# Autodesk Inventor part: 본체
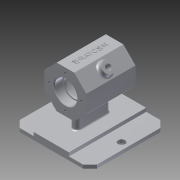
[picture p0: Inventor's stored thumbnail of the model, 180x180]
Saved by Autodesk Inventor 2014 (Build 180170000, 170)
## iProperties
Created: 2018-06
Part Number: 본체
Material: Aluminum 6061
Document SubType Name: Modeling
Designer: kh
Density: 2.71 g/cm^3
Appearance: Aluminum - Flat
Mass: 554.078 g
Surface Area: 602.069 cm^2
Volume: 204.457 cm^3
Author: kh
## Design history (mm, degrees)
sketch "Sketch1"
  geometry: 1 further point
sketch "Sketch2"
  geometry: L1 (-55, -55)-(55, -55); L2 (55, -55)-(55, 55); L3 (55, 55)-(-55, 55); L4 (-55, 55)-(-55, -55); L5 (-55, -55)-(55, 55); L6 (55, -55)-(-55, 55); 1 further point
  constraints: 12 end point, 2 midpoint, 2 parallel, 1 horizontal, 1 perpendicular
  dimensions: "d0" = 110 distance of L2.end L3.end; "d1" = 110 distance of L1.end L2.end
extrude "Extrusion1" new body sketch "Sketch2" distance "d2" = 5; taper "d3" = 0 deg
sketch "Sketch3"
  geometry: L1 (-55, 55)-(-55, -55) reference; L2 (55, -55)-(55, 55) reference; L3 (-55, -25)-(55, -25); L4 (55, -25)-(55, 25); L5 (55, 25)-(-55, 25); L6 (-55, 25)-(-55, -25); L7 (-55, -25)-(55, 25); L8 (55, -25)-(-55, 25); L9 (55, 55)-(-55, 55) reference; L10 (-55, -55)-(55, -55) reference; 1 further point
  constraints: 12 end point, 2 midpoint, 2 parallel, 1 horizontal, 1 perpendicular, 1 point on line
  dimensions: "d4" = 30 distance between parallel lines of L9 L5
extrude "Extrusion2" join sketch "Sketch3" distance "d5" = 5; taper "d6" = 0 deg
sketch "Sketch4"
  geometry: 1 further point
sketch "Sketch5" dims "d7" = 60
  geometry: L1 (12.426, 92)-(30, 74.426); L2 (30, 74.426)-(30, 49.574); L3 (30, 49.574)-(12.426, 32); L4 (12.426, 32)-(-12.426, 32); L5 (-12.426, 32)-(-30, 49.574); L6 (-30, 49.574)-(-30, 74.426); L7 (-30, 74.426)-(-12.426, 92); L8 (-12.426, 92)-(12.426, 92); 4 further points
  constraints: 16 end point, 2 vertical alignment, 1 coincident, 1 midpoint, 19 other
  dimensions: "d10" = 62 distance of point (0, 62) point (0, 0); "d12" = 17.57359 horizontal distance of L1.start L1.end
extrude "Extrusion3" join sketch "Sketch5" stored distance "d13" = 70; taper "d14" = 0 deg
sketch "Sketch6"
  geometry: 1 further point
sketch "Sketch7" dims "d15" = 46
  geometry: L1 (-74.426, 30)-(-92, 12.426) reference; L2 (-92, 12.426)-(-92, -12.426) reference; L3 (-92, -12.426)-(-74.426, -30) reference; L4 (-74.426, -30)-(-49.574, -30) reference; L5 (-49.574, -30)-(-32, -12.426) reference; L6 (-32, -12.426)-(-32, 12.426) reference; L7 (-32, 12.426)-(-49.574, 30) reference; L8 (-49.574, 30)-(-74.426, 30) reference; L9 (-49.574, 30)-(-74.426, -30); L10 (-74.426, 30)-(-49.574, -30); L11 (-92, -12.426)-(-32, 12.426); L12 (-62, 0)-(-85, 0); C1 r 16 at (-62, 0); 2 further points
  constraints: 8 end point, 2 coincident, 1 centre point, 1 horizontal alignment, 1 midpoint, 1 parallel, 1 perpendicular, 1 point on line, 2 other
  dimensions: "d34" = 32 diameter of C1
  node "Projected Loop1"
hole "Hole1" sketch "Sketch7" diameter "d16" = 3.242; stored, may be unused: countersink angle "d20" = 90 deg, drill point angle "d22" = 118 deg; dims "d17" = 8, "d18" = 4, "d19" = 2, "d21" = 10
sketch "Sketch11"
  geometry: L1 (55, 55)-(-55, 55) reference; L2 (-55, -55)-(55, -55) reference; C1 r 5 at (0, 45); 1 further point
  constraints: 1 centre point, 1 vertical alignment
  dimensions: "d25" = 10 diameter of C1; "d26" = 10 distance from line of L1 C1.centre
extrude "Extrusion4" cut sketch "Sketch11" stored distance "d27" = 70; taper "d28" = 0 deg
mirror "Mirror1"
sketch "Sketch12"
  geometry: L1 (19, 0)-(-19, 0); L2 (19, 5)-(-19, 5); L3 (-19, -5)-(19, -5); A1 r 5 centre (19, 0) between (19, -5) and (19, 5); A2 r 5 centre (-19, 0) between (-19, 5) and (-19, -5); 1 further point
  constraints: 8 end point, 4 point on circle, 4 tangent, 2 centre point, 1 horizontal, 1 midpoint, 1 parallel
  dimensions: "d29" = 38 distance of L1.end L1.start; "d30" = 5 radius of A1
extrude "Extrusion5" join sketch "Sketch12" stored distance "d31" = 70; taper "d32" = 0 deg
fillet "Fillet1" dims "d33" = 2
extrude "Extrusion6" cut sketch "Sketch7" distance "d35" = 12; taper "d36" = 0 deg
pattern_circular "Circular Pattern1" dims angle "d38" = 360 deg
hole "Hole2" diameter "d43" = 28; stored, may be unused: countersink angle "d47" = 90 deg, drill point angle "d49" = 0 deg; dims "d41" = 10, "d42" = 10, "d44" = 8, "d45" = 4, "d46" = 2, "d48" = 3
sketch "Sketch16"
  geometry: L1 (-30, -12.426)-(-30, 12.426) reference; L2 (-30, 12.426)-(-12.426, 30) reference; L3 (-12.426, 30)-(12.426, 30) reference; L4 (12.426, 30)-(30, 12.426) reference; L5 (30, 12.426)-(30, -12.426) reference; L6 (30, -12.426)-(12.426, -30) reference; L7 (12.426, -30)-(-12.426, -30) reference; L8 (-12.426, -30)-(-30, -12.426) reference; L9 (-30, -12.426)-(-30, 12.426) reference; L10 (-30, 12.426)-(30, -12.426); L11 (30, 12.426)-(-30, -12.426); C1 r 25 at (0, 0); 2 further points
  constraints: 4 end point, 3 midpoint, 1 centre point, 1 coincident, 1 point on line
  dimensions: "d50" = 50 diameter of C1
extrude "Extrusion7" cut sketch "Sketch16" distance "d51" = 40; taper "d52" = 0 deg
mirror "Mirror2"
mirror "Mirror3"
workplane "Work Plane2"
sketch "Sketch18"
  geometry: L1 (70, 24.853)-(0, 24.853) reference; L2 (0, 0)-(70, 0) reference; L3 (70, 24.853)-(70, 0) reference; L4 (0, 0)-(0, 24.853) reference; L5 (0, 12.426)-(83.367, 12.426); C1 r 8 at (35, 12.426); 1 further point
  constraints: 2 end point, 1 centre point, 1 midpoint, 1 perpendicular, 1 point on line
  dimensions: "d55" = 16 diameter of C1; "d56" = 35 distance from line of L3 C1.centre
extrude "Extrusion8" join sketch "Sketch18" stored distance "d59" = 40; taper "d60" = 0 deg
sketch "Sketch19"
  geometry: C1 r 8 at (0, 0) reference; C2 r 4 at (0, 0); 1 further point
  constraints: 1 centre point, 1 coincident
  dimensions: "d61" = 8 diameter of C2
extrude "Extrusion9" cut sketch "Sketch19" stored distance "d62" = 8 (= d61); taper "d63" = 0 deg
fillet "Fillet2" dims "d64" = 1
fillet "Fillet3" dims "d65" = 3
chamfer "Chamfer1" distance "d66" = 10; stored, may be unused: second distance "d67" = 2, angle "d68" = 45 deg
sketch "Sketch21"
  geometry: L1 (70, -17.695)-(0, -17.695) reference; L2 (70, -0.707)-(70, -17.695) reference; 2 further points
  constraints: 1 other
  dimensions: "d72" = 30 distance from line of L1 point (35, 12.305); "d73" = 35 distance from line of L2 point (35, 12.305)
emboss "Emboss1" sketch "Sketch21" dims "d5" = 5, "d6" = 0, "d74" = 0.5, "d75" = 0
chamfer "Chamfer2" distance "d76" = 1; stored, may be unused: second distance "d77" = 2, angle "d78" = 45 deg
fillet "Fillet4" dims "d79" = 0.3
fillet "Fillet5" dims "d80" = 3
body "Solid1"
node "Projected Loop3"
other parameters: "d54" = 7
